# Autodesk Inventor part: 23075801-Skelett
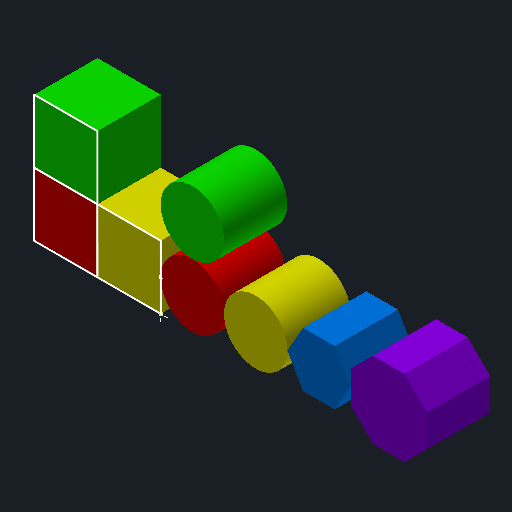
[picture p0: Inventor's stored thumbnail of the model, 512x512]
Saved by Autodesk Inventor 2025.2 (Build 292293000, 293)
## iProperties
Company: Ed. Züblin AG
Created: 2025-03
Part Number: 23075801-Skelett
Material: Stahlbeton C30/37
Document SubType Name: Modeling
Designer: FrodlSte
Mass: 1.80321e+07 g
Surface Area: 428504 cm^2
Volume: 7.21282e+06 cm^3
Density: 2.5 g/cm^3
Appearance: Beton C30/37
z_Bereich: Tunnelbau
z_Direktion: Tief- und Tunnelbau
z_Konzerneinheit: Zentrale Technik
z_Matchkey: =<z_Matchkey_010>_<z_Matchkey_020>_<z_Matchkey_030>_<z_Matchkey_040>_<z_Matchkey_050>_<z_Matchkey_060>_<z_Matchkey_070>_<z_Matchkey_080>_<z_Matchkey_090>_<z_Mat
cpiComponentType: Attribut
cpiFitMatchkey: =<z_Matchkey>
z_Matchkey_010: xxxxx
z_Matchkey_020: 5DTUB
z_Matchkey_030: xxx
z_Matchkey_040: xxx
z_Matchkey_050: xxx
z_Matchkey_060: xxx
z_Matchkey_070: xxx
z_Matchkey_080: xxx
z_Matchkey_090: xxx
z_Matchkey_100: xxx
z_Matchkey_110: xxx
z_Matchkey_120: xxxxxxx
z_Matchkey_130: xxxx
z_Matchkey_140: xxxx
DocNumber: 23075801-Skelett.ipt
Folder: DL23075801-DE-Pfaffensteigtunnel\BIM\Testmodell
VDS_Category: 09 - BIM - Konstruktion
AS_Ta_IST: 0,300 m
AS_Abs_L_So: 2,000 m
AS_Td_IST: 3,000 m
AS_Ti_IST: 3,000 m
AS_U_IST: 4,000 m
IS_T_b_M1: 1,000 m
AS_Abs_L_Ka: 1,000 m
DR_D_i: 0,250 m
AS_Dak_IST: 0,030 m
AS_Dad_IST: 0,010 m
Author: FrodlSte
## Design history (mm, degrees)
node "Blöcke"
  sketch "Baugruppe_Quadrate"
    geometry: L1 (0, 0)-(1000, 0) reference; L2 (1000, 0)-(1000, 1000) reference; L3 (1000, 1000)-(0, 1000) reference; L4 (0, 1000)-(0, 0) reference; L5 (1000, 0)-(2000, 0) reference; L6 (2000, 0)-(2000, 1000) reference; L7 (2000, 1000)-(1000, 1000) reference; L8 (1000, 1000)-(1000, 0) reference; L9 (1000, 1000)-(2000, 1000) reference; L10 (2000, 1000)-(2000, 2000) reference; L11 (2000, 2000)-(1000, 2000) reference; L12 (1000, 2000)-(1000, 1000) reference; 3 further points
    constraints: 24 end point, 6 parallel, 3 horizontal, 3 perpendicular, 2 coincident, 1 midpoint
    dimensions: "d4_1" = 1000 distance of L3.end L2.end; "d5" = 1000 distance of L1.end L2.end; "d6" = 1000 distance of L7.end L6.end; "d7" = 1000 distance of L5.end L6.end; "d8" = 1000 distance of L11.end L10.end; "d9" = 1000 distance of L10.end L9.end
  sketch "Baugruppe_Kreise"
    geometry: C1 r 500 at (-500, 500) reference; C2 r 500 at (-1500, 500) reference; C3 r 500 at (-500, 1500) reference; 2 further points
    constraints: 3 centre point, 2 equal radius, 1 coincident, 1 horizontal alignment, 1 vertical alignment
    dimensions: "d10" = 1000 diameter of C1; "d11" = 1000 diameter of C2; "d12" = 1000 diameter of C3
  sketch "Bauteil_Sechseck"
    geometry: L1 (-2250, 933.013)-(-2000, 500) reference; L2 (-2000, 500)-(-2250, 66.987) reference; L3 (-2250, 66.987)-(-2750, 66.987) reference; L4 (-2750, 66.987)-(-3000, 500) reference; L5 (-3000, 500)-(-2750, 933.013) reference; L6 (-2750, 933.013)-(-2250, 933.013) reference; 3 further points
    constraints: 12 end point, 1 horizontal, 13 other
    dimensions: "d13" = 500 distance of L5.end L1.start
  sketch "Bauteil_Achteck"
    geometry: L1 (-3353.553, 1103.553)-(-3000, 750) reference; L2 (-3000, 250)-(-3353.553, -103.553) reference; L3 (-3353.553, -103.553)-(-3853.553, -103.553) reference; L4 (-3853.553, -103.553)-(-4207.107, 250) reference; L5 (-4207.107, 250)-(-4207.107, 750) reference; L6 (-4207.107, 750)-(-3853.553, 1103.553) reference; L7 (-3853.553, 1103.553)-(-3353.553, 1103.553) reference; L8 (-3000, 750)-(-3000, 250) reference; 2 further points
    constraints: 16 end point, 1 coincident, 1 horizontal, 1 vertical
    dimensions: "d15" = 500 distance of L6.end L1.start
derived "23075801-Test_Regelquerschnitt.ipt"
sketch "Skizze - Quadrate"
  geometry: 3 further points
  constraints: 1 other
  node "Baugruppe_Quadrate:1"
sketch "Skizze - Kreise"
  geometry: 1 further point
  constraints: 1 other
  node "Baugruppe_Kreise:1"
sketch "Skizze - Sechseck"
  geometry: 1 further point
  constraints: 1 other
  node "Bauteil_Sechseck:1"
sketch "Skizze6"
  geometry: 1 further point
  constraints: 1 other
  node "Bauteil_Achteck:1"
extrude "Extrusion3" new body sketch "Skizze - Quadrate" distance "d14" = 1000 (= Länge_Quadrate); taper "d16" = 0 deg
extrude "Extrusion4" new body sketch "Skizze - Quadrate" distance "d17" = 1000 (= Länge_Quadrate); taper "d18" = 0 deg
extrude "Extrusion5" new body sketch "Skizze - Quadrate" distance "d19" = 1000 (= Länge_Quadrate); taper "d20" = 0 deg
extrude "Extrusion6" new body sketch "Skizze - Kreise" distance "d21" = 1000 (= Länge_Kreise); taper "d22" = 0 deg
extrude "Extrusion7" new body sketch "Skizze - Kreise" distance "d23" = 1000 (= Länge_Kreise); taper "d24" = 0 deg
extrude "Extrusion8" new body sketch "Skizze - Kreise" distance "d25" = 1000 (= Länge_Kreise); taper "d26" = 0 deg
extrude "Extrusion9" new body sketch "Skizze - Sechseck" distance "d27" = 1000 (= Länge_Sechseck); taper "d28" = 0 deg
extrude "Extrusion10" new body sketch "Skizze6" distance "d29" = 1000 (= Länge_Achteck); taper "d30" = 0 deg
node "Quadrat_1"
node "Volumenkörpern"
node "Oberflächenkörpern"
node "Quadrat_2"
node "Quadrat_3"
node "Kreis_1"
node "Kreis_2"
node "Kreis_3"
node "Sechseck"
node "Achteck"
other parameters: "Länge_Quadrate" = 1000 [user parameter; used in 3 equation terms], "Länge_Kreise" = 1000 [user parameter; used in 3 equation terms], "Länge_Sechseck" = 1000 [user parameter; used in 1 equation term], "Länge_Achteck" = 1000 [user parameter; used in 1 equation term], "AS_Ta_IST" = 300, "AS_Abs_L_So" = 2000, "AS_Td_IST" = 3000, "AS_Ti_IST" = 3000, "AS_U_IST" = 4000, "IS_T_b_M1" = 1000, "AS_Abs_L_Ka" = 1000, "DR_D_i" = 250, "AS_Dak_IST" = 30, "AS_Dad_IST" = 10
